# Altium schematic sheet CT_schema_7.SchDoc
size 368 x 245 mm
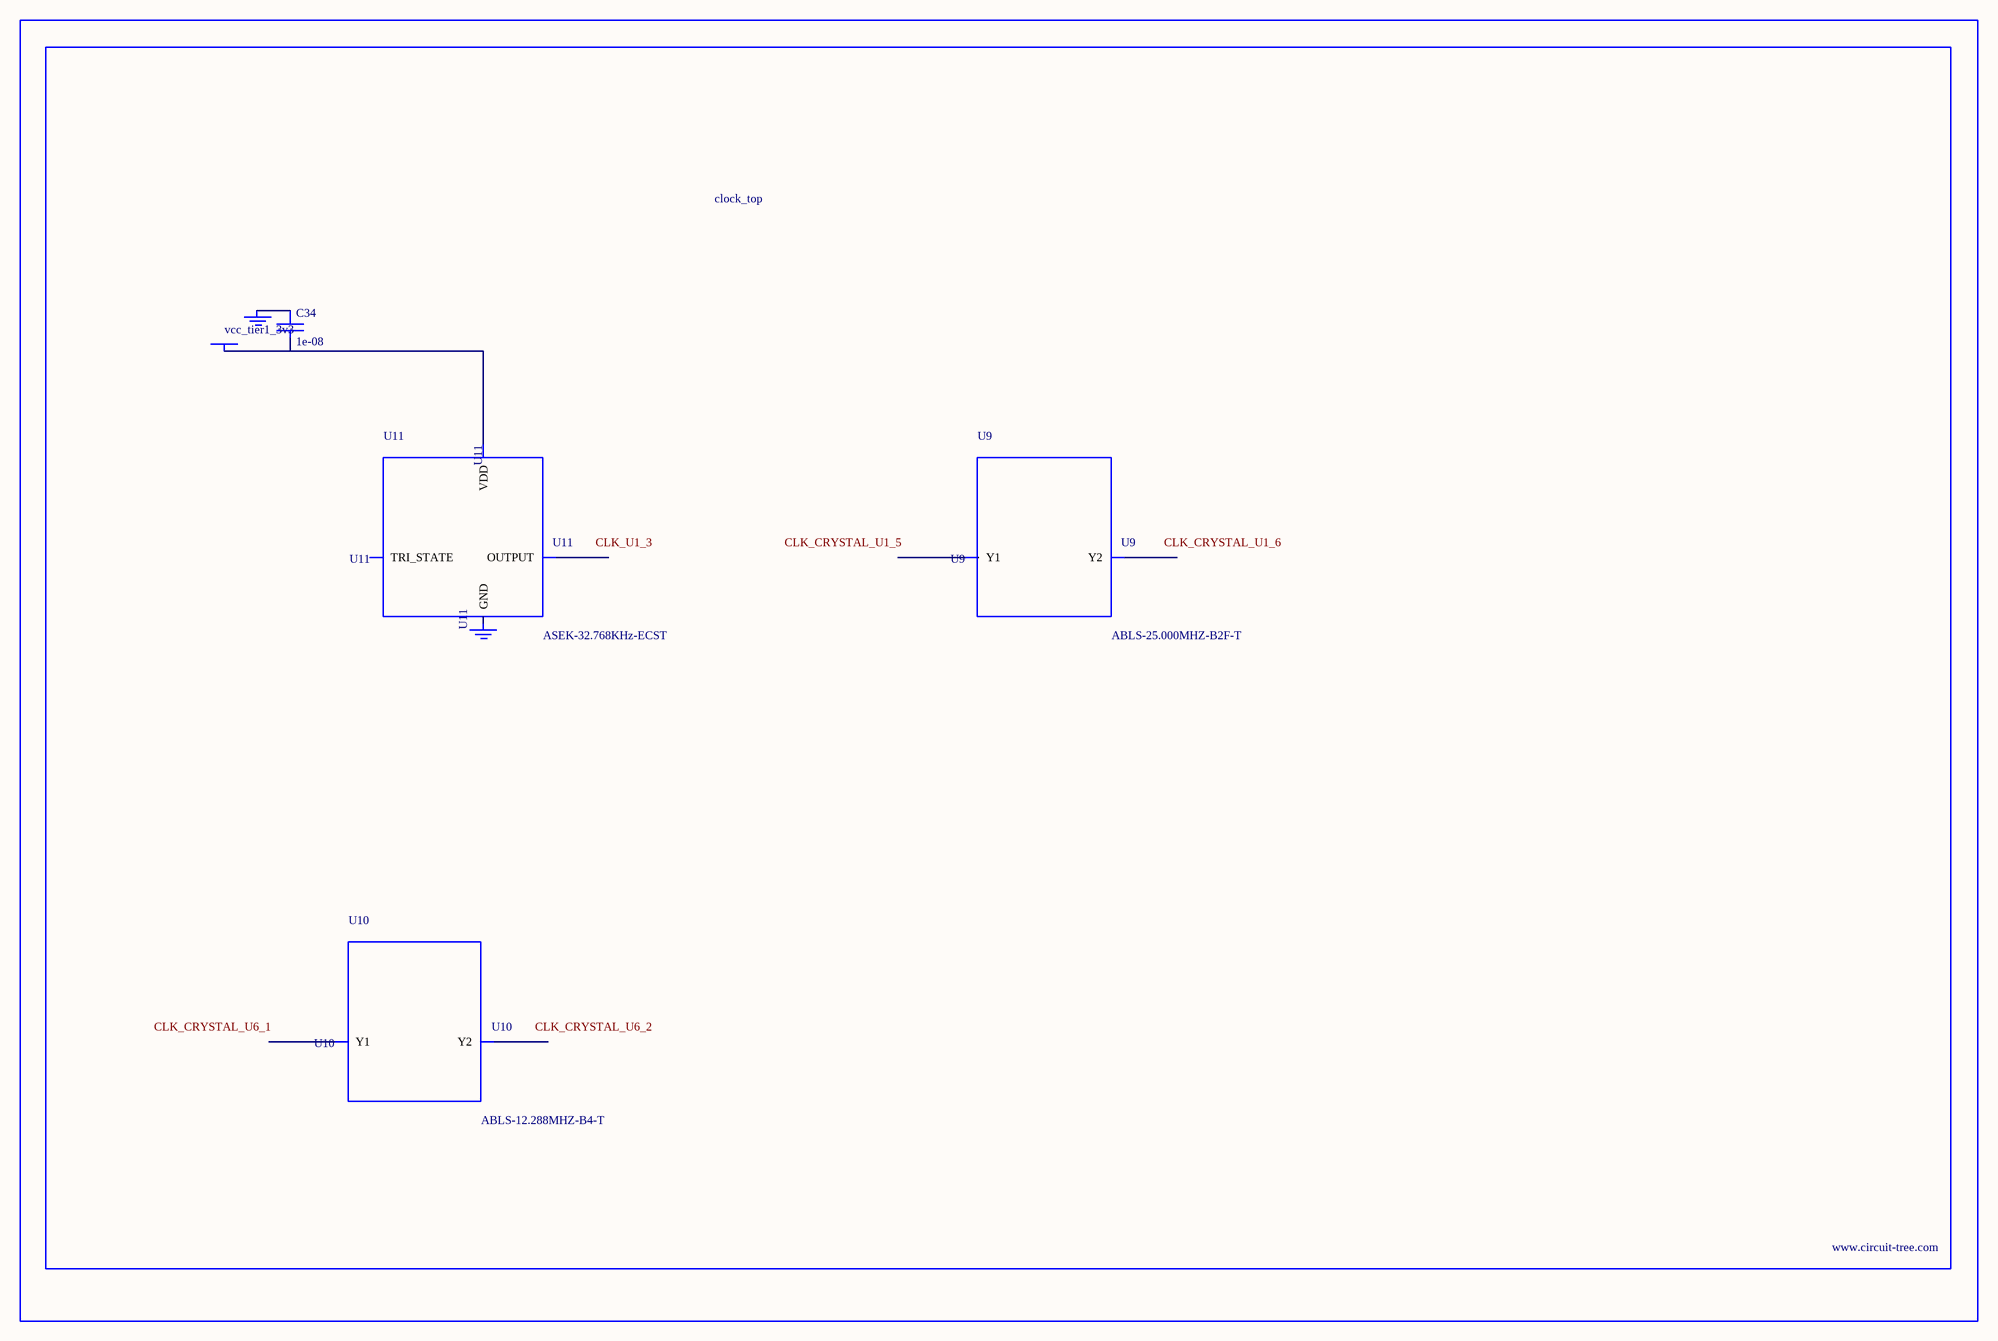
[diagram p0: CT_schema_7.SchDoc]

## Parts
BORDER6  (no value)
C34  1e-08  [C0402]
GND_INSTANCE_6_0  (no value)
GND_INSTANCE_6_1  (no value)
POWER_INSTANCE_6_0  vcc_tier1_3v3
U9  ABLS-25.000MHZ-B2F-T  [ABLS-25.000MHZ-B2F-T]
U10  ABLS-12.288MHZ-B4-T  [ABLS-12.288MHZ-B4-T]
U11  ASEK-32.768KHz-ECST  [ASEK]

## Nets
NetC34_1: C34.1 GND_INSTANCE_6_0.0(GND)
NetC34_2: C34.2 POWER_INSTANCE_6_0.0(PWR) U11.4(VDD)

Not connected (* = marked no-connect by the designer): GND_INSTANCE_6_1 0(GND); U9 1(Y1) 2(Y2); U10 1(Y1) 2(Y2); U11 1(TRI_STATE) 2(GND) 3(OUTPUT)

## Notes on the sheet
- Labels drawn without touching a wire or pin: CLK_CRYSTAL_U1_5, CLK_CRYSTAL_U1_6, CLK_CRYSTAL_U6_1, CLK_CRYSTAL_U6_2, CLK_U1_3

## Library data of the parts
BORDER6 = BORDER_PAGE6
C34 = C0402C103K3RAC
GND_INSTANCE_6_0 GND_INSTANCE_6_1 = GND
POWER_INSTANCE_6_0 = PWR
